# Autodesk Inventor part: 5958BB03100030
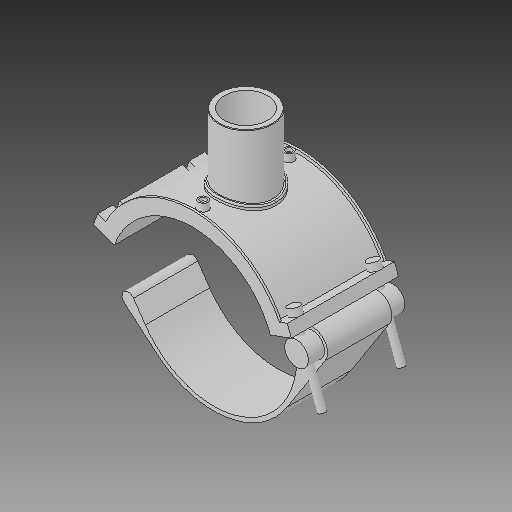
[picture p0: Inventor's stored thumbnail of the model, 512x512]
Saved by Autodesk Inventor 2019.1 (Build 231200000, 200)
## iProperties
Created: 2017-07
Part Number: 5958BB03100030
Material: Generic
Description: PLASSON BRANCH SADDLE 10'' x 3''
Document SubType Name: Modeling
Designer: KIM
Mass: 764.267 g
Surface Area: 1930.38 cm^2
Volume: 764.267 cm^3
Density: 1 g/cm^3
Appearance: Default
Author: KIM
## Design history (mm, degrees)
derived "5958B.ipt"
feature "Solid1::5958B.ipt"
feature "Solid2::5958B.ipt"
feature "Solid3::5958B.ipt"
tag "TaggingFeature1"
body "Solid1"
body "Solid2"
body "Solid3"
other parameters: "d0" = 272.7, "d2" = 234.7722, "d3" = 68.175, "d4" = 176.022, "d5" = 0, "d6" = 0.1, "d8" = 0, "d19" = 6, "d20" = 6, "d21" = 105.6132, "d23" = 0, "d24" = 52.8066, "d26" = 0, "d27" = 3, "d28" = 3, "d29" = 3, "d30" = 90.9, "d31" = 6, "d32" = 0, "d33" = 0, "d34" = 0.6, "d40" = 160.82352, "d41" = 97.57, "d43" = 0, "d45" = 0, "d47" = 261.572, "d48" = 88.7, "d50" = 0, "d70" = 15, "d72" = 0, "d73" = 6, "d75" = 5, "d76" = 0, "d77" = 13.635, "d78" = 166.35, "d79" = 15, "d80" = 70.4088, "d82" = 5 deg, "d84" = 4, "d85" = 14, "d86" = 0, "d87" = 3, "d88" = 0, "d89" = 1, "d90" = 1, "d91" = 140.8176, "d92" = 0, "d93" = 0.5, "d94" = 143.52632, "d96" = 315.46152, "d97" = 3.52044, "d98" = 0, "d102" = 2.661, "d103" = 70.96, "d105" = 0, "d109" = -35.64467, "d117" = 0.887, "d120" = 140 deg, "d121" = 24.228, "d122" = 20 deg, "d123" = 618.552, "d124" = 185.5656, "d126" = 0, "d143" = 286.335, "d150" = 49.086, "d159" = 7.3152, "d161" = 6.8175, "d162" = 105.6132, "d163" = 0, "d167" = 54.54, "d168" = 140.58, "d173" = 1, "d175" = 136.35, "d176" = 20 deg, "d177" = 19.089, "d178" = 36.576, "d180" = 0, "d185" = 57.20715, "d186" = 57.20715, "d187" = 154.638, "d188" = 10.9728, "d189" = 19.089, "d190" = 0, "d191" = 231.957, "d200" = 18.288, "d202" = 0, "d216" = 158.4198, "d217" = 0, "d221" = 65.12814, "d222" = 19.089, "d223" = 11.4534, "d224" = 136.35, "d225" = 11.4534, "d227" = 39.2688, "d230" = 162.2565, "d236" = 11.5 deg, "d238" = 20 deg, "d239" = 19.089, "d240" = 3.52044, "d241" = 0, "d242" = 5.454, "d_" = 272.7, "B_" = 180.594, "H_" = 106.934, "L_" = 176.022, "d_t" = 6, "d_1" = 88.7, "H_1" = 88.646, "d1" = 309.276, "d148" = 6.8175, "d160" = 6.8175
